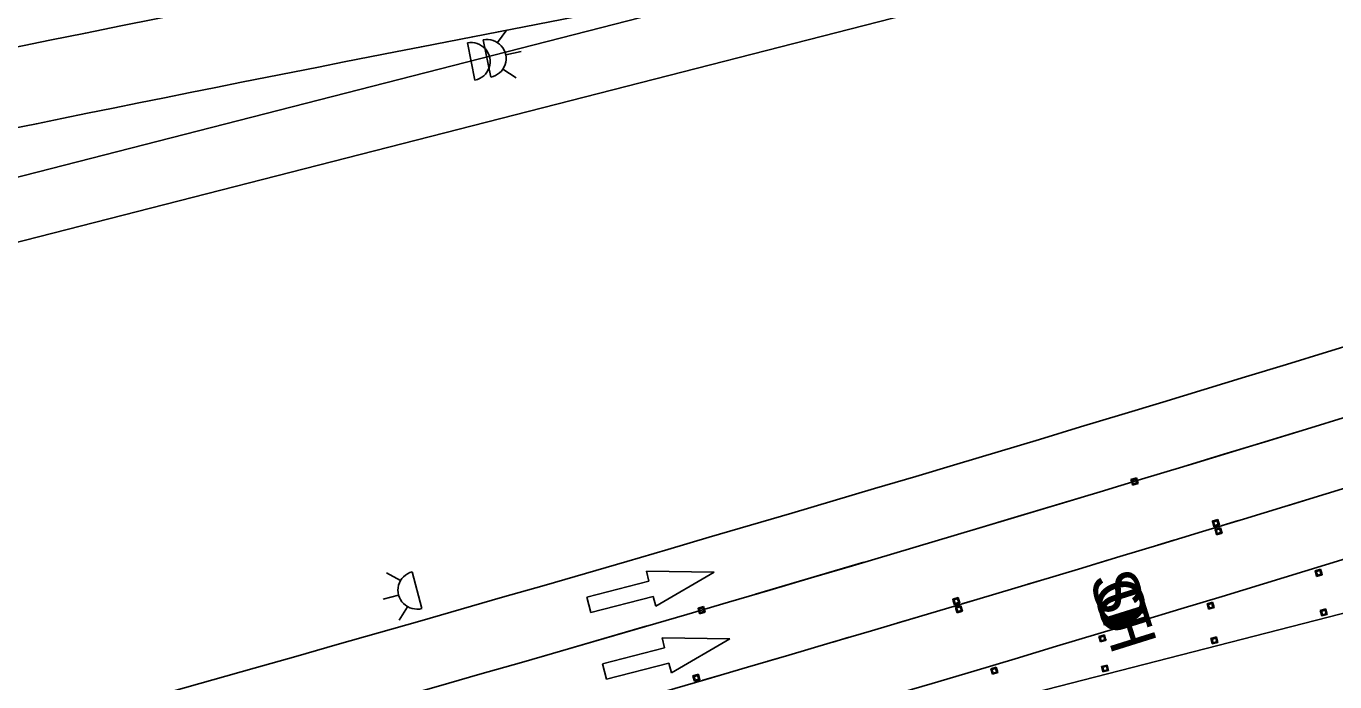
# Model space of a CAD drawing. Extents: x 2471014 to 2497726, y 6959577 to 6980268.
# Drawn here: x 2486020.2 to 2486252, y 6968251.5 to 6968367.7 of the extents above; entities that cross this region are included whole.
import ezdxf

# ---------------------------------------------------------------- set-up
doc = ezdxf.new("R2010")
doc.units = 0
for name, color, linetype in [('13', 7, 'Continuous'), ('23', 7, 'Continuous'), ('25', 7, 'Continuous'), ('5', 7, 'Continuous'), ('59', 7, 'Continuous'), ('ALIGN_ML_IH35_NB_SB', 7, 'Continuous'), ('Level 40', 7, 'Continuous'), ('p_structure fence', 7, 'Continuous'), ('PMK_Del_D-SY_SZ_TYC_CTB', 7, 'Continuous'), ('RDWY_PAVE_XSTREET_FOC', 7, 'Continuous'), ('S-BRDG-BENT', 7, 'Continuous'), ('SHADE SW', 7, 'Continuous'), ('V7_25', 7, 'Continuous')]:
    doc.layers.add(name, color=color, linetype=linetype)

msp = doc.modelspace()

# ---------------------------------------------------------------- linework, layer by layer
at = {"layer": '13'}
for centre, start, end in [((2487721.19, 6960022.02), 100.374936, 104.374936), ((2483751.61, 6976434.35), 284.374936, 287.663843)]:
    msp.add_arc(centre, 8500, start, end, dxfattribs=at)
at = {"layer": '23'}
for p, q in [((2486215.9, 6968287.39), (2486216.87, 6968287.68)), ((2486216.11, 6968287.29), (2486215.9, 6968287.39)), ((2486215.9, 6968287.39), (2486215.98, 6968287.13)), ((2486215.98, 6968287.13), (2486216.2, 6968286.42)), ((2486216.31, 6968286.64), (2486216.11, 6968287.29)), ((2486217.17, 6968286.71), (2486216.2, 6968286.42)), ((2486216.2, 6968286.42), (2486216.31, 6968286.64)), ((2486216.87, 6968287.68), (2486216.76, 6968287.48)), ((2486216.76, 6968287.48), (2486216.8, 6968287.35)), ((2486216.8, 6968287.35), (2486216.95, 6968286.83)), ((2486217.17, 6968286.71), (2486216.87, 6968287.68)), ((2486216.95, 6968286.83), (2486217.17, 6968286.71)), ((2486230.32, 6968280), (2486231.29, 6968280.3)), ((2486230.52, 6968279.9), (2486230.32, 6968280)), ((2486230.32, 6968280), (2486230.39, 6968279.75)), ((2486230.39, 6968279.75), (2486230.61, 6968279.03)), ((2486230.72, 6968279.25), (2486230.52, 6968279.9)), ((2486231.58, 6968279.33), (2486230.61, 6968279.03)), ((2486230.61, 6968279.03), (2486230.72, 6968279.25)), ((2486230.78, 6968278.56), (2486231.75, 6968278.86)), ((2486230.99, 6968278.46), (2486230.78, 6968278.56)), ((2486230.78, 6968278.56), (2486230.86, 6968278.31)), ((2486231.29, 6968280.3), (2486231.17, 6968280.1)), ((2486231.17, 6968280.1), (2486231.21, 6968279.96)), ((2486231.21, 6968279.96), (2486231.37, 6968279.45)), ((2486231.58, 6968279.33), (2486231.29, 6968280.3)), ((2486231.37, 6968279.45), (2486231.58, 6968279.33)), ((2486231.75, 6968278.86), (2486231.63, 6968278.66)), ((2486231.63, 6968278.66), (2486231.67, 6968278.52)), ((2486231.67, 6968278.52), (2486231.83, 6968278.01)), ((2486232.04, 6968277.89), (2486231.75, 6968278.86)), ((2486230.86, 6968278.31), (2486231.07, 6968277.59)), ((2486231.18, 6968277.81), (2486230.99, 6968278.46)), ((2486232.04, 6968277.89), (2486231.07, 6968277.59)), ((2486231.07, 6968277.59), (2486231.18, 6968277.81)), ((2486231.83, 6968278.01), (2486232.04, 6968277.89)), ((2486248.51, 6968271.2), (2486249.48, 6968271.49)), ((2486248.72, 6968271.08), (2486248.51, 6968271.2)), ((2486248.51, 6968271.2), (2486248.8, 6968270.23)), ((2486248.88, 6968270.56), (2486248.72, 6968271.08)), ((2486249.77, 6968270.52), (2486248.8, 6968270.23)), ((2486248.8, 6968270.23), (2486248.92, 6968270.43)), ((2486248.92, 6968270.43), (2486248.88, 6968270.56)), ((2486249.48, 6968271.49), (2486249.37, 6968271.28)), ((2486249.37, 6968271.28), (2486249.57, 6968270.63)), ((2486249.7, 6968270.78), (2486249.48, 6968271.49)), ((2486249.57, 6968270.63), (2486249.77, 6968270.52)), ((2486249.77, 6968270.52), (2486249.7, 6968270.78)), ((2486139.23, 6968264.59), (2486140.2, 6968264.87)), ((2486140.2, 6968264.87), (2486140.08, 6968264.67)), ((2486140.08, 6968264.67), (2486140.12, 6968264.54)), ((2486140.48, 6968263.9), (2486140.2, 6968264.87)), ((2486184.35, 6968266.18), (2486185.33, 6968266.47)), ((2486184.56, 6968266.07), (2486184.35, 6968266.18)), ((2486184.35, 6968266.18), (2486184.43, 6968265.92)), ((2486184.43, 6968265.92), (2486184.64, 6968265.2)), ((2486184.75, 6968265.42), (2486184.56, 6968266.07)), ((2486185.62, 6968265.49), (2486184.64, 6968265.2)), ((2486184.64, 6968265.2), (2486184.75, 6968265.42)), ((2486184.82, 6968264.73), (2486185.79, 6968265.02)), ((2486185.02, 6968264.63), (2486184.82, 6968264.73)), ((2486184.82, 6968264.73), (2486184.89, 6968264.48)), ((2486185.22, 6968263.98), (2486185.02, 6968264.63)), ((2486185.33, 6968266.47), (2486185.21, 6968266.26)), ((2486185.21, 6968266.26), (2486185.25, 6968266.13)), ((2486185.25, 6968266.13), (2486185.4, 6968265.61)), ((2486185.62, 6968265.49), (2486185.33, 6968266.47)), ((2486185.4, 6968265.61), (2486185.62, 6968265.49)), ((2486185.79, 6968265.02), (2486185.67, 6968264.82)), ((2486185.67, 6968264.82), (2486185.71, 6968264.69)), ((2486185.71, 6968264.69), (2486185.87, 6968264.17)), ((2486186.08, 6968264.05), (2486185.79, 6968265.02)), ((2486229.38, 6968265.37), (2486230.35, 6968265.66)), ((2486229.59, 6968265.25), (2486229.38, 6968265.37)), ((2486229.38, 6968265.37), (2486229.67, 6968264.4)), ((2486229.75, 6968264.74), (2486229.59, 6968265.25)), ((2486230.64, 6968264.69), (2486229.67, 6968264.4)), ((2486229.79, 6968264.6), (2486229.75, 6968264.74)), ((2486230.35, 6968265.66), (2486230.24, 6968265.45)), ((2486230.24, 6968265.45), (2486230.43, 6968264.8)), ((2486230.56, 6968264.95), (2486230.35, 6968265.66)), ((2486230.43, 6968264.8), (2486230.64, 6968264.69)), ((2486230.64, 6968264.69), (2486230.56, 6968264.95)), ((2486139.43, 6968264.48), (2486139.23, 6968264.59)), ((2486139.23, 6968264.59), (2486139.3, 6968264.33)), ((2486139.3, 6968264.33), (2486139.51, 6968263.62)), ((2486139.62, 6968263.83), (2486139.43, 6968264.48)), ((2486140.48, 6968263.9), (2486139.51, 6968263.62)), ((2486139.51, 6968263.62), (2486139.62, 6968263.83)), ((2486140.12, 6968264.54), (2486140.27, 6968264.02)), ((2486140.27, 6968264.02), (2486140.48, 6968263.9)), ((2486184.89, 6968264.48), (2486185.11, 6968263.76)), ((2486186.08, 6968264.05), (2486185.11, 6968263.76)), ((2486185.11, 6968263.76), (2486185.22, 6968263.98)), ((2486185.87, 6968264.17), (2486186.08, 6968264.05)), ((2486229.67, 6968264.4), (2486229.79, 6968264.6)), ((2486249.44, 6968264.2), (2486250.42, 6968264.45)), ((2486249.65, 6968264.07), (2486249.44, 6968264.2)), ((2486249.44, 6968264.2), (2486249.69, 6968263.22)), ((2486249.78, 6968263.55), (2486249.65, 6968264.07)), ((2486250.68, 6968263.47), (2486249.69, 6968263.22)), ((2486249.69, 6968263.22), (2486249.82, 6968263.41)), ((2486249.82, 6968263.41), (2486249.78, 6968263.55)), ((2486250.42, 6968264.45), (2486250.31, 6968264.24)), ((2486250.31, 6968264.24), (2486250.47, 6968263.58)), ((2486250.61, 6968263.73), (2486250.42, 6968264.45)), ((2486250.47, 6968263.58), (2486250.68, 6968263.47)), ((2486250.68, 6968263.47), (2486250.61, 6968263.73)), ((2486210.23, 6968259.59), (2486211.2, 6968259.88)), ((2486210.45, 6968259.47), (2486210.23, 6968259.59)), ((2486210.23, 6968259.59), (2486210.52, 6968258.62)), ((2486210.6, 6968258.95), (2486210.45, 6968259.47)), ((2486211.5, 6968258.91), (2486210.52, 6968258.62)), ((2486210.52, 6968258.62), (2486210.64, 6968258.82)), ((2486210.64, 6968258.82), (2486210.6, 6968258.95)), ((2486211.2, 6968259.88), (2486211.09, 6968259.66)), ((2486211.09, 6968259.66), (2486211.29, 6968259.01)), ((2486211.42, 6968259.17), (2486211.2, 6968259.88)), ((2486211.29, 6968259.01), (2486211.5, 6968258.91)), ((2486211.5, 6968258.91), (2486211.42, 6968259.17)), ((2486230.07, 6968259.23), (2486231.05, 6968259.49)), ((2486230.28, 6968259.11), (2486230.07, 6968259.23)), ((2486230.07, 6968259.23), (2486230.32, 6968258.25)), ((2486230.41, 6968258.59), (2486230.28, 6968259.11)), ((2486231.3, 6968258.5), (2486230.32, 6968258.25)), ((2486230.32, 6968258.25), (2486230.44, 6968258.45)), ((2486230.44, 6968258.45), (2486230.41, 6968258.59)), ((2486231.05, 6968259.49), (2486230.93, 6968259.27)), ((2486230.93, 6968259.27), (2486231.1, 6968258.62)), ((2486231.23, 6968258.77), (2486231.05, 6968259.49)), ((2486231.1, 6968258.62), (2486231.3, 6968258.5)), ((2486231.3, 6968258.5), (2486231.23, 6968258.77)), ((2486191.07, 6968253.85), (2486192.05, 6968254.14)), ((2486191.29, 6968253.73), (2486191.07, 6968253.85)), ((2486191.07, 6968253.85), (2486191.36, 6968252.88)), ((2486191.44, 6968253.21), (2486191.29, 6968253.73)), ((2486192.34, 6968253.17), (2486191.36, 6968252.88)), ((2486191.36, 6968252.88), (2486191.48, 6968253.08)), ((2486191.48, 6968253.08), (2486191.44, 6968253.21)), ((2486192.05, 6968254.14), (2486191.94, 6968253.92)), ((2486191.94, 6968253.92), (2486192.13, 6968253.27)), ((2486192.26, 6968253.43), (2486192.05, 6968254.14)), ((2486192.13, 6968253.27), (2486192.34, 6968253.17)), ((2486192.34, 6968253.17), (2486192.26, 6968253.43)), ((2486210.69, 6968254.27), (2486211.68, 6968254.52)), ((2486210.9, 6968254.14), (2486210.69, 6968254.27)), ((2486210.69, 6968254.27), (2486210.94, 6968253.29)), ((2486211.03, 6968253.62), (2486210.9, 6968254.14)), ((2486211.93, 6968253.54), (2486210.94, 6968253.29)), ((2486210.94, 6968253.29), (2486211.07, 6968253.48)), ((2486211.07, 6968253.48), (2486211.03, 6968253.62)), ((2486211.68, 6968254.52), (2486211.56, 6968254.31)), ((2486211.56, 6968254.31), (2486211.73, 6968253.65)), ((2486211.86, 6968253.8), (2486211.68, 6968254.52)), ((2486211.73, 6968253.65), (2486211.93, 6968253.54)), ((2486211.93, 6968253.54), (2486211.86, 6968253.8)), ((2486138.32, 6968252.6), (2486139.29, 6968252.89)), ((2486138.52, 6968252.5), (2486138.32, 6968252.6)), ((2486138.32, 6968252.6), (2486138.39, 6968252.35)), ((2486138.39, 6968252.35), (2486138.6, 6968251.63)), ((2486138.71, 6968251.85), (2486138.52, 6968252.5)), ((2486139.57, 6968251.91), (2486138.6, 6968251.63)), ((2486138.6, 6968251.63), (2486138.71, 6968251.85)), ((2486139.29, 6968252.89), (2486139.17, 6968252.69)), ((2486139.17, 6968252.69), (2486139.21, 6968252.55)), ((2486139.21, 6968252.55), (2486139.36, 6968252.04)), ((2486139.57, 6968251.91), (2486139.29, 6968252.89)), ((2486139.36, 6968252.04), (2486139.57, 6968251.91))]:
    msp.add_line(p, q, dxfattribs=at)
for points in [[(2486216.11, 6968287.29), (2486216.76, 6968287.48), (2486216.95, 6968286.83), (2486216.31, 6968286.64)], [(2486230.52, 6968279.9), (2486231.17, 6968280.1), (2486231.37, 6968279.45), (2486230.72, 6968279.25)], [(2486230.99, 6968278.46), (2486231.63, 6968278.66), (2486231.83, 6968278.01), (2486231.18, 6968277.81)], [(2486249.57, 6968270.63), (2486248.92, 6968270.43), (2486248.72, 6968271.08), (2486249.37, 6968271.28)], [(2486139.43, 6968264.48), (2486140.08, 6968264.67), (2486140.27, 6968264.02), (2486139.62, 6968263.83)], [(2486184.56, 6968266.07), (2486185.21, 6968266.26), (2486185.4, 6968265.61), (2486184.75, 6968265.42)], [(2486185.02, 6968264.63), (2486185.67, 6968264.82), (2486185.87, 6968264.17), (2486185.22, 6968263.98)], [(2486230.43, 6968264.8), (2486229.79, 6968264.6), (2486229.59, 6968265.25), (2486230.24, 6968265.45)], [(2486250.47, 6968263.58), (2486249.82, 6968263.41), (2486249.65, 6968264.07), (2486250.31, 6968264.24)], [(2486211.29, 6968259.01), (2486210.64, 6968258.82), (2486210.45, 6968259.47), (2486211.09, 6968259.66)], [(2486231.1, 6968258.62), (2486230.44, 6968258.45), (2486230.28, 6968259.11), (2486230.93, 6968259.27)], [(2486192.13, 6968253.27), (2486191.48, 6968253.08), (2486191.29, 6968253.73), (2486191.94, 6968253.92)], [(2486211.73, 6968253.65), (2486211.07, 6968253.48), (2486210.9, 6968254.14), (2486211.56, 6968254.31)], [(2486138.52, 6968252.5), (2486139.17, 6968252.69), (2486139.36, 6968252.04), (2486138.71, 6968251.85)]]:
    msp.add_lwpolyline(points, close=True, dxfattribs=at)
at = {"layer": '25'}
msp.add_line((2485870.81, 6968165.59), (2486321.17, 6968281.02), dxfattribs=at)
for centre, radius, start, end in [((2487979.84, 6960100.7), 8500, 101.888901, 104.374936), ((2487721.19, 6960022.02), 8514, 100.374936, 103.133014), ((2483751.61, 6976434.35), 8536, 284.374936, 287.663843)]:
    msp.add_arc(centre, radius, start, end, dxfattribs=at)
at = {"layer": '5'}
msp.add_arc((2479474.04, 6969335.88), 8460, 6.37617, 6.37617, dxfattribs=at)
at = {"layer": '59'}
msp.add_arc((2483751.61, 6976434.35), 8524, 284.374936, 287.663843, dxfattribs=at)
at = {"layer": 'ALIGN_ML_IH35_NB_SB'}
for p, q in [((2486119.51, 6968266.57), (2486130.52, 6968269.39)), ((2486130.52, 6968269.39), (2486130.08, 6968271.14)), ((2486130.08, 6968271.14), (2486142.07, 6968270.99)), ((2486142.07, 6968270.99), (2486131.73, 6968264.93)), ((2486120.21, 6968263.84), (2486119.51, 6968266.57)), ((2486131.28, 6968266.68), (2486120.21, 6968263.84)), ((2486131.73, 6968264.93), (2486131.28, 6968266.68)), ((2486133.31, 6968257.58), (2486132.86, 6968259.32)), ((2486132.86, 6968259.32), (2486144.85, 6968259.17)), ((2486144.85, 6968259.17), (2486134.51, 6968253.12)), ((2486122.29, 6968254.75), (2486133.31, 6968257.58)), ((2486122.99, 6968252.02), (2486122.29, 6968254.75)), ((2486134.06, 6968254.86), (2486122.99, 6968252.02)), ((2486134.51, 6968253.12), (2486134.06, 6968254.86))]:
    msp.add_line(p, q, dxfattribs=at)
at = {"layer": 'Level 40'}
for p, q in [((2486243.57, 6968282.74), (2486246.44, 6968283.62)), ((2486232.09, 6968279.24), (2486234.96, 6968280.11)), ((2486220.61, 6968275.76), (2486223.48, 6968276.63)), ((2486209.12, 6968272.29), (2486211.99, 6968273.15)), ((2486197.63, 6968268.84), (2486200.5, 6968269.7)), ((2486186.13, 6968265.4), (2486189, 6968266.26)), ((2486174.62, 6968261.98), (2486177.5, 6968262.84)), ((2486163.12, 6968258.58), (2486165.99, 6968259.43)), ((2486151.61, 6968255.19), (2486154.48, 6968256.04)), ((2486140.09, 6968251.82), (2486142.97, 6968252.66))]:
    msp.add_line(p, q, dxfattribs=at)
at = {"layer": 'PMK_Del_D-SY_SZ_TYC_CTB'}
for p, q in [((2486086.53, 6968269.47), (2486084.07, 6968270.85)), ((2486090.32, 6968264.53), (2486088.58, 6968271.05)), ((2486086.19, 6968266.91), (2486083.47, 6968266.18)), ((2486087.76, 6968264.86), (2486086.26, 6968262.48))]:
    msp.add_line(p, q, dxfattribs=at)
msp.add_arc((2486089.45, 6968267.79), 3.37, 104.997, 284.997, dxfattribs=at)
at = {"layer": 'RDWY_PAVE_XSTREET_FOC'}
for p, q in [((2486226.08, 6968289.96), (2486245.21, 6968295.79)), ((2486187.78, 6968278.42), (2486206.94, 6968284.17)), ((2486149.43, 6968267.06), (2486168.61, 6968272.72)), ((2486111.02, 6968255.88), (2486130.23, 6968261.45))]:
    msp.add_line(p, q, dxfattribs=at)
at = {"layer": 'S-BRDG-BENT'}
msp.add_line((2485246.23, 6968131.47), (2487181.35, 6968627.42), dxfattribs=at)
msp.add_line((2485246.23, 6968131.47), (2487181.35, 6968627.42), dxfattribs=at)
at = {"layer": 'SHADE SW'}
for p, q in [((2486103.71, 6968364.82), (2486105.36, 6968367.1)), ((2486098.37, 6968364.78), (2486099.71, 6968358.16)), ((2486101.18, 6968365.31), (2486102.52, 6968358.7)), ((2486105.16, 6968362.67), (2486107.91, 6968363.23)), ((2486104.66, 6968360.14), (2486107.02, 6968358.61))]:
    msp.add_line(p, q, dxfattribs=at)
for centre in [(2486099.04, 6968361.47), (2486101.85, 6968362)]:
    msp.add_arc(centre, 3.37, 281.4144, 101.4144, dxfattribs=at)
at = {"layer": 'V7_25'}
msp.add_line((2485243.45, 6968142.32), (2487178.57, 6968638.27), dxfattribs=at)
for centre, radius, start, end in [((2487979.84, 6960100.7), 8524, 101.888901, 104.374936), ((2487979.84, 6960100.7), 8524, 101.888901, 104.374936), ((2487979.84, 6960100.7), 8512, 101.888901, 104.374936), ((2487979.84, 6960100.7), 8512, 101.888901, 104.374936), ((2483751.61, 6976434.35), 8512, 284.374936, 287.663843)]:
    msp.add_arc(centre, radius, start, end, dxfattribs=at)

# ---------------------------------------------------------------- texts
at = {"layer": 'p_structure fence'}
for s, p in [('S', (2486208.46, 6968269.88)), ('O', (2486208.95, 6968268.33)), ('U', (2486209.46, 6968266.7)), ('T', (2486209.95, 6968265.17)), ('H', (2486210.43, 6968263.62))]:
    msp.add_text(s, height=8.2, rotation=287.4283, dxfattribs=at).set_placement(p)

doc.saveas('drawing.dxf')
